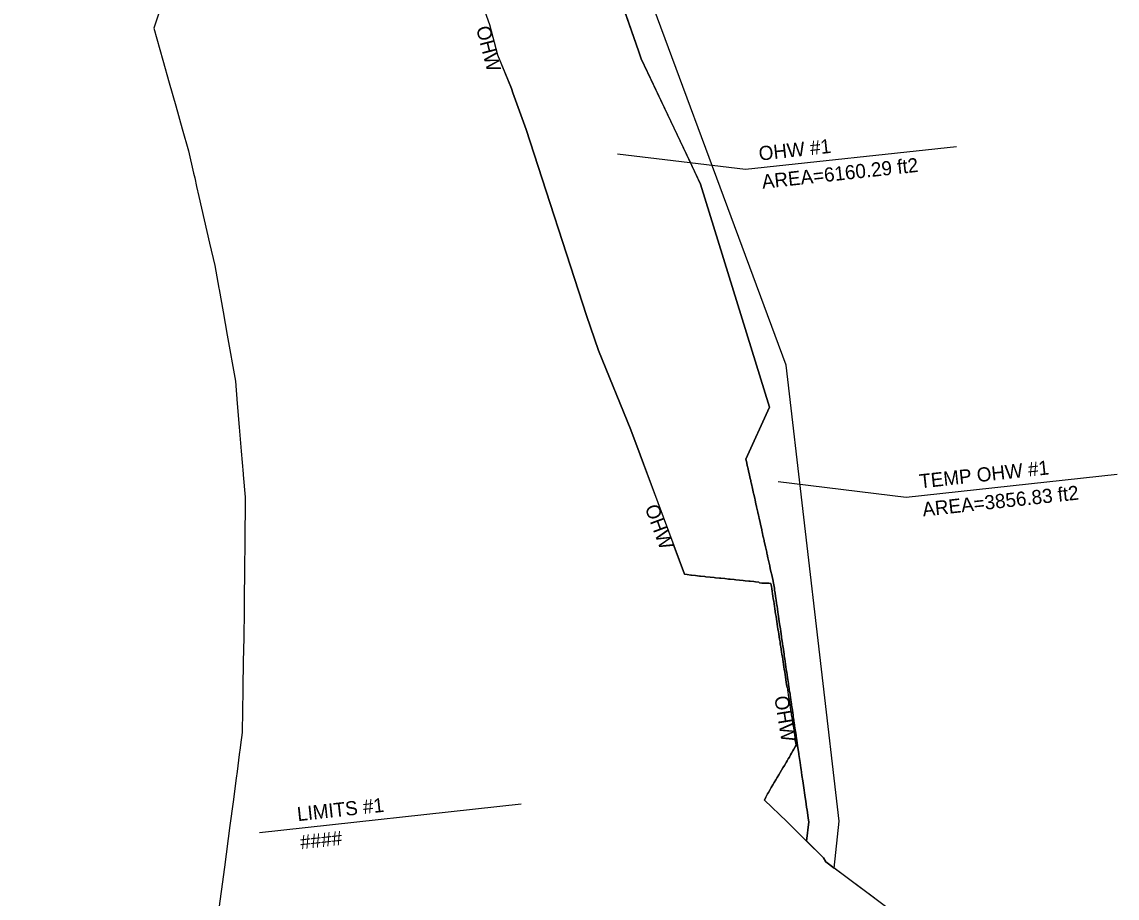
# Model space of a CAD drawing. Extents: x 1509537 to 1510685, y 401169 to 402194.
# Drawn here: x 1509714.7 to 1509931.6, y 401562.2 to 401735.7 of the extents above; entities that cross this region are included whole.
import ezdxf

# ---------------------------------------------------------------- set-up
doc = ezdxf.new("R2010")
doc.units = 0
for name, color, linetype in [('LAWE', 7, 'Continuous'), ('LAWE_P', 7, 'Continuous'), ('LAWE_P_T', 7, 'Continuous'), ('Level 6', 7, 'Continuous'), ('Level 9', 7, 'Continuous')]:
    doc.layers.add(name, color=color, linetype=linetype)

msp = doc.modelspace()

# ---------------------------------------------------------------- linework, layer by layer
at = {"layer": 'LAWE'}
for points in [[(1509840.19, 401641.87), (1509837.17, 401650.02), (1509835.36, 401654.93), (1509828.91, 401670.68), (1509826.52, 401677.61), (1509814.57, 401714.41), (1509811.96, 401721.64), (1509811.67, 401722.52), (1509809.89, 401726.86)], [(1509866.28, 401603.91), (1509866.27, 401603.95), (1509866.18, 401604.52), (1509866.12, 401604.95), (1509866.02, 401605.52), (1509865.96, 401605.95), (1509865.87, 401606.53), (1509865.8, 401606.95), (1509865.71, 401607.53), (1509865.65, 401607.95), (1509865.56, 401608.53), (1509865.49, 401608.95), (1509865.4, 401609.53), (1509865.34, 401609.95), (1509865.24, 401610.53), (1509865.18, 401610.95), (1509865.09, 401611.53), (1509865.03, 401611.95), (1509864.93, 401612.53), (1509864.87, 401612.95), (1509864.78, 401613.53), (1509864.71, 401613.96), (1509864.62, 401614.53), (1509864.56, 401614.96), (1509864.46, 401615.53), (1509864.4, 401615.96), (1509864.31, 401616.53), (1509864.25, 401616.96), (1509864.15, 401617.54), (1509864.09, 401617.96), (1509864, 401618.54), (1509863.94, 401618.96), (1509863.84, 401619.54), (1509863.78, 401619.96), (1509863.69, 401620.54), (1509863.62, 401620.96), (1509863.53, 401621.54), (1509863.47, 401621.96), (1509863.37, 401622.54), (1509863.31, 401622.96), (1509863.22, 401623.54), (1509863.16, 401623.96), (1509863.06, 401624.54), (1509862.66, 401624.58), (1509862.15, 401624.56), (1509861.73, 401624.6), (1509861.24, 401624.58), (1509860.8, 401624.62), (1509860.7, 401624.78), (1509860, 401624.86), (1509859.7, 401624.89), (1509858.98, 401624.96), (1509858.7, 401625), (1509857.97, 401625.07), (1509857.6, 401625.11), (1509856.87, 401625.18), (1509856.13, 401625.26), (1509855.78, 401625.3), (1509855.03, 401625.37), (1509854.7, 401625.41), (1509853.95, 401625.48), (1509853.17, 401625.56), (1509852.88, 401625.6), (1509852.09, 401625.67), (1509851.81, 401625.7), (1509851.03, 401625.78), (1509850.21, 401625.86), (1509849.97, 401625.89), (1509849.15, 401625.97), (1509848.93, 401626), (1509848.11, 401626.08), (1509847.37, 401626.17), (1509847.24, 401626.19), (1509846.49, 401626.29), (1509845.93, 401626.36), (1509843.7, 401632.37)], [(1509888.15, 401558.82), (1509873.96, 401569.39), (1509873.47, 401570.24), (1509866.19, 401577.38), (1509861.77, 401581.65), (1509862.07, 401582.21), (1509862.42, 401582.85), (1509862.6, 401583.15), (1509862.92, 401583.73), (1509863.15, 401584.11), (1509863.47, 401584.68), (1509863.72, 401585.12), (1509864.04, 401585.65), (1509864.3, 401586.1), (1509864.62, 401586.63), (1509864.88, 401587.07), (1509865.17, 401587.55), (1509865.45, 401588.01), (1509865.73, 401588.46), (1509866.01, 401588.93), (1509866.07, 401589.06), (1509866.27, 401589.39), (1509866.51, 401589.84), (1509866.72, 401590.17), (1509866.96, 401590.62), (1509867.16, 401590.95), (1509867.4, 401591.4), (1509867.6, 401591.73), (1509867.85, 401592.18), (1509868.05, 401592.51), (1509867.98, 401592.94), (1509867.89, 401593.51), (1509867.83, 401593.91)]]:
    msp.add_lwpolyline(points, dxfattribs=at)
at = {"layer": 'LAWE_P'}
for p, q in [((1509836.93, 401729.78), (1509831.74, 401744.61)), ((1509836.94, 401729.77), (1509836.93, 401729.78)), ((1509837.39, 401728.38), (1509836.94, 401729.77)), ((1509847.13, 401707.85), (1509837.39, 401728.38)), ((1509858.28, 401648.4), (1509858.13, 401649.11)), ((1509858.48, 401647.51), (1509858.46, 401647.63)), ((1509858.71, 401646.49), (1509858.48, 401647.51)), ((1509858.76, 401646.27), (1509858.71, 401646.49)), ((1509859.1, 401644.73), (1509859.06, 401644.94)), ((1509859.16, 401644.48), (1509859.1, 401644.73)), ((1509859.35, 401643.63), (1509859.29, 401643.9)), ((1509860.11, 401640.21), (1509859.92, 401641.09)), ((1509860.19, 401639.86), (1509860.11, 401640.21)), ((1509860.58, 401638.14), (1509860.49, 401638.53)), ((1509861.25, 401635.12), (1509860.99, 401636.27)), ((1509861.26, 401635.07), (1509861.25, 401635.12)), ((1509861.34, 401634.7), (1509861.26, 401635.07)), ((1509861.39, 401634.51), (1509861.34, 401634.7)), ((1509861.71, 401633.06), (1509861.59, 401633.58)), ((1509861.75, 401632.86), (1509861.71, 401633.06)), ((1509862.24, 401630.71), (1509862, 401631.76)), ((1509862.24, 401630.68), (1509862.24, 401630.71)), ((1509862.29, 401630.48), (1509862.24, 401630.68)), ((1509862.55, 401629.31), (1509862.48, 401629.61)), ((1509863.15, 401626.6), (1509862.95, 401627.52)), ((1509863.18, 401626.49), (1509863.15, 401626.6)), ((1509863.45, 401625.28), (1509863.18, 401626.49)), ((1509863.6, 401624.58), (1509863.45, 401625.28)), ((1509863.7, 401623.94), (1509863.6, 401624.58)), ((1509863.75, 401623.58), (1509863.7, 401623.94)), ((1509863.81, 401623.17), (1509863.75, 401623.58)), ((1509864.09, 401621.27), (1509864.05, 401621.57)), ((1509864.2, 401620.56), (1509864.09, 401621.27)), ((1509864.28, 401619.98), (1509864.2, 401620.56)), ((1509864.34, 401619.56), (1509864.28, 401619.98)), ((1509864.47, 401618.7), (1509864.34, 401619.56)), ((1509864.49, 401618.56), (1509864.47, 401618.7)), ((1509864.79, 401616.55), (1509864.66, 401617.44)), ((1509865.02, 401614.99), (1509864.94, 401615.54)), ((1509865.08, 401614.54), (1509865.02, 401614.99)), ((1509865.09, 401614.51), (1509865.08, 401614.54)), ((1509865.16, 401614.05), (1509865.09, 401614.51)), ((1509865.19, 401613.79), (1509865.16, 401614.05)), ((1509865.38, 401612.53), (1509865.37, 401612.61)), ((1509865.68, 401610.52), (1509865.54, 401611.44)), ((1509865.71, 401610.29), (1509865.68, 401610.52)), ((1509865.97, 401608.51), (1509865.88, 401609.15)), ((1509866.37, 401605.82), (1509866.27, 401606.5)), ((1509866.71, 401603.49), (1509866.69, 401603.65)), ((1509866.85, 401602.58), (1509866.71, 401603.49)), ((1509867.13, 401600.67), (1509867.01, 401601.48)), ((1509867.31, 401599.41), (1509867.31, 401599.47)), ((1509867.62, 401597.34), (1509867.6, 401597.46)), ((1509867.75, 401596.46), (1509867.62, 401597.34)), ((1509867.77, 401596.31), (1509867.75, 401596.46)), ((1509867.9, 401595.46), (1509867.77, 401596.31)), ((1509867.92, 401595.29), (1509867.9, 401595.46)), ((1509868.05, 401594.46), (1509867.92, 401595.29)), ((1509868.19, 401593.45), (1509868.07, 401594.27)), ((1509868.34, 401592.44), (1509868.19, 401593.45)), ((1509868.84, 401589.08), (1509868.61, 401590.64)), ((1509869.96, 401581.45), (1509869.86, 401582.13)), ((1509870.19, 401579.94), (1509870.14, 401580.26))]:
    msp.add_line(p, q, dxfattribs=at)
for points in [[(1509795.89, 401767.18), (1509807.37, 401735.22), (1509808.92, 401729.22), (1509811.67, 401722.52), (1509811.96, 401721.64), (1509814.57, 401714.41), (1509826.52, 401677.61), (1509828.91, 401670.68), (1509835.36, 401654.93), (1509837.17, 401650.02), (1509840.68, 401640.55), (1509845.93, 401626.36), (1509846.49, 401626.29), (1509847.24, 401626.19), (1509847.37, 401626.17), (1509848.11, 401626.08), (1509848.93, 401626), (1509849.15, 401625.97), (1509849.97, 401625.89), (1509850.21, 401625.86), (1509851.03, 401625.78), (1509851.81, 401625.7), (1509852.09, 401625.67), (1509852.88, 401625.6), (1509853.17, 401625.56), (1509853.95, 401625.48), (1509854.7, 401625.41), (1509855.03, 401625.37), (1509855.78, 401625.3), (1509856.13, 401625.26), (1509856.87, 401625.18), (1509857.6, 401625.11), (1509857.97, 401625.07), (1509858.7, 401625), (1509858.98, 401624.96), (1509859.7, 401624.89), (1509860, 401624.86), (1509860.7, 401624.78), (1509860.8, 401624.62), (1509861.24, 401624.58), (1509861.73, 401624.6), (1509862.15, 401624.56), (1509862.66, 401624.58), (1509863.06, 401624.54), (1509863.16, 401623.96), (1509863.22, 401623.54), (1509863.31, 401622.96), (1509863.37, 401622.54), (1509863.47, 401621.96), (1509863.53, 401621.54), (1509863.62, 401620.96), (1509863.69, 401620.54), (1509863.78, 401619.96), (1509863.84, 401619.54), (1509863.94, 401618.96), (1509864, 401618.54), (1509864.09, 401617.96), (1509864.15, 401617.54), (1509864.25, 401616.96), (1509864.31, 401616.53), (1509864.4, 401615.96), (1509864.46, 401615.53), (1509864.56, 401614.96), (1509864.62, 401614.53), (1509864.71, 401613.96), (1509864.78, 401613.53), (1509864.87, 401612.95), (1509864.93, 401612.53), (1509865.03, 401611.95), (1509865.09, 401611.53), (1509865.18, 401610.95), (1509865.24, 401610.53), (1509865.34, 401609.95), (1509865.4, 401609.53), (1509865.49, 401608.95), (1509865.56, 401608.53), (1509865.65, 401607.95), (1509865.71, 401607.53), (1509865.8, 401606.95), (1509865.87, 401606.53), (1509865.96, 401605.95), (1509866.02, 401605.52), (1509866.12, 401604.95), (1509866.18, 401604.52), (1509866.27, 401603.95), (1509866.33, 401603.52), (1509866.43, 401602.95), (1509866.49, 401602.52), (1509866.58, 401601.95), (1509866.65, 401601.52), (1509866.74, 401600.95), (1509866.8, 401600.52), (1509866.89, 401599.95), (1509866.96, 401599.52), (1509867.05, 401598.94), (1509867.11, 401598.52), (1509867.21, 401597.94), (1509867.27, 401597.52), (1509867.36, 401596.94), (1509867.42, 401596.52), (1509867.52, 401595.94), (1509867.58, 401595.51), (1509867.67, 401594.94), (1509867.74, 401594.51), (1509867.83, 401593.94), (1509867.89, 401593.51), (1509867.98, 401592.94), (1509868.05, 401592.51), (1509867.85, 401592.18), (1509867.6, 401591.73), (1509867.4, 401591.4), (1509867.16, 401590.95), (1509866.96, 401590.62), (1509866.72, 401590.17), (1509866.51, 401589.84), (1509866.27, 401589.39), (1509866.07, 401589.06), (1509866.01, 401588.93), (1509865.73, 401588.46), (1509865.45, 401588.01), (1509865.17, 401587.55), (1509864.88, 401587.07), (1509864.62, 401586.63), (1509864.3, 401586.1), (1509864.04, 401585.65), (1509863.72, 401585.12), (1509863.47, 401584.68), (1509863.15, 401584.11), (1509862.92, 401583.73), (1509862.6, 401583.15), (1509862.42, 401582.85), (1509862.07, 401582.21), (1509861.77, 401581.65), (1509866.19, 401577.38), (1509870.13, 401573.51)], [(1509858.13, 401649.11), (1509862.77, 401659.41), (1509849.15, 401703.58), (1509847.13, 401707.85)], [(1509858.46, 401647.63), (1509858.31, 401648.29), (1509858.28, 401648.4)], [(1509859.06, 401644.94), (1509858.98, 401645.3), (1509858.76, 401646.27)], [(1509859.29, 401643.9), (1509859.27, 401643.99), (1509859.16, 401644.48)], [(1509859.92, 401641.09), (1509859.86, 401641.35), (1509859.66, 401642.23), (1509859.64, 401642.35), (1509859.49, 401643.02), (1509859.35, 401643.63)], [(1509860.49, 401638.53), (1509860.46, 401638.64), (1509860.34, 401639.19), (1509860.22, 401639.72), (1509860.19, 401639.86)], [(1509860.73, 401637.45), (1509860.67, 401637.7), (1509860.58, 401638.14)], [(1509860.99, 401636.27), (1509860.92, 401636.58), (1509860.73, 401637.45)], [(1509861.59, 401633.58), (1509861.5, 401633.98), (1509861.39, 401634.51)], [(1509862, 401631.76), (1509861.92, 401632.13), (1509861.75, 401632.86)], [(1509862.48, 401629.61), (1509862.32, 401630.33), (1509862.29, 401630.48)], [(1509862.95, 401627.52), (1509862.85, 401627.94), (1509862.84, 401627.99), (1509862.72, 401628.56), (1509862.55, 401629.31)], [(1509864.05, 401621.57), (1509863.9, 401622.57), (1509863.9, 401622.6), (1509863.81, 401623.17)], [(1509864.66, 401617.44), (1509864.64, 401617.55), (1509864.5, 401618.47), (1509864.49, 401618.56)], [(1509864.94, 401615.54), (1509864.84, 401616.21), (1509864.79, 401616.55)], [(1509865.37, 401612.61), (1509865.23, 401613.53), (1509865.19, 401613.79)], [(1509865.54, 401611.44), (1509865.53, 401611.53), (1509865.38, 401612.53)], [(1509865.88, 401609.15), (1509865.82, 401609.52), (1509865.78, 401609.84), (1509865.71, 401610.29)], [(1509866.27, 401606.5), (1509866.21, 401606.92), (1509866.12, 401607.51), (1509866.04, 401608.03), (1509865.97, 401608.51)], [(1509866.53, 401604.73), (1509866.42, 401605.5), (1509866.37, 401605.82)], [(1509866.69, 401603.65), (1509866.57, 401604.5), (1509866.53, 401604.73)], [(1509867.01, 401601.48), (1509867, 401601.51), (1509866.94, 401601.93), (1509866.86, 401602.49), (1509866.85, 401602.58)], [(1509867.31, 401599.47), (1509867.16, 401600.46), (1509867.16, 401600.48), (1509867.13, 401600.67)], [(1509867.6, 401597.46), (1509867.5, 401598.15), (1509867.47, 401598.38), (1509867.45, 401598.47), (1509867.31, 401599.41)], [(1509868.07, 401594.27), (1509868.05, 401594.45), (1509868.05, 401594.46)], [(1509868.61, 401590.64), (1509868.58, 401590.81), (1509868.34, 401592.44)], [(1509869.65, 401583.58), (1509869.51, 401584.51), (1509869.37, 401585.46), (1509869.21, 401586.52), (1509869.12, 401587.19), (1509869.04, 401587.72), (1509868.99, 401588.03), (1509868.84, 401589.08)], [(1509869.86, 401582.13), (1509869.72, 401583.08), (1509869.65, 401583.58)], [(1509870.14, 401580.26), (1509870.05, 401580.83), (1509869.96, 401581.45)], [(1509870.13, 401573.51), (1509870.56, 401577.36), (1509870.47, 401578.03), (1509870.22, 401579.72), (1509870.19, 401579.94)]]:
    msp.add_lwpolyline(points, dxfattribs=at)
at = {"layer": 'LAWE_P_T'}
msp.add_line((1509761.82, 401575.22), (1509813.64, 401580.87), dxfattribs=at)
for points in [[(1509832.69, 401709.61), (1509858.05, 401706.52), (1509899.82, 401711.07)], [(1509864.49, 401644.73), (1509889.85, 401641.63), (1509931.62, 401646.19)]]:
    msp.add_lwpolyline(points, dxfattribs=at)
at = {"layer": 'Level 6'}
for p, q in [((1509836.94, 401729.77), (1509837.39, 401728.38)), ((1509858.13, 401649.11), (1509858.28, 401648.4)), ((1509858.28, 401648.4), (1509858.31, 401648.29)), ((1509859.06, 401644.94), (1509859.1, 401644.73)), ((1509859.1, 401644.73), (1509859.16, 401644.48)), ((1509859.49, 401643.02), (1509859.64, 401642.35)), ((1509859.64, 401642.35), (1509859.66, 401642.23)), ((1509859.66, 401642.23), (1509859.86, 401641.35)), ((1509859.86, 401641.35), (1509859.92, 401641.09)), ((1509859.92, 401641.09), (1509860.11, 401640.21)), ((1509860.11, 401640.21), (1509860.19, 401639.86)), ((1509860.19, 401639.86), (1509860.22, 401639.72)), ((1509860.22, 401639.72), (1509860.34, 401639.19)), ((1509860.49, 401638.53), (1509860.58, 401638.14)), ((1509860.92, 401636.58), (1509860.99, 401636.27)), ((1509861.34, 401634.7), (1509861.39, 401634.51)), ((1509861.71, 401633.06), (1509861.75, 401632.86)), ((1509861.75, 401632.86), (1509861.92, 401632.13)), ((1509862.24, 401630.68), (1509862.29, 401630.48)), ((1509862.29, 401630.48), (1509862.32, 401630.33)), ((1509862.32, 401630.33), (1509862.48, 401629.61)), ((1509862.48, 401629.61), (1509862.55, 401629.31)), ((1509862.55, 401629.31), (1509862.72, 401628.56)), ((1509863.15, 401626.6), (1509863.18, 401626.49)), ((1509863.18, 401626.49), (1509863.45, 401625.28)), ((1509863.7, 401623.94), (1509863.75, 401623.58)), ((1509863.9, 401622.6), (1509863.9, 401622.57)), ((1509863.9, 401622.57), (1509864.05, 401621.57)), ((1509864.05, 401621.57), (1509864.09, 401621.27)), ((1509864.09, 401621.27), (1509864.2, 401620.56)), ((1509864.2, 401620.56), (1509864.28, 401619.98)), ((1509864.28, 401619.98), (1509864.34, 401619.56)), ((1509864.34, 401619.56), (1509864.47, 401618.7)), ((1509864.47, 401618.7), (1509864.49, 401618.56)), ((1509864.49, 401618.56), (1509864.5, 401618.47)), ((1509864.66, 401617.44), (1509864.79, 401616.55)), ((1509864.79, 401616.55), (1509864.84, 401616.21)), ((1509864.84, 401616.21), (1509864.94, 401615.54)), ((1509865.08, 401614.54), (1509865.09, 401614.51)), ((1509865.09, 401614.51), (1509865.16, 401614.05)), ((1509865.37, 401612.61), (1509865.38, 401612.53)), ((1509865.38, 401612.53), (1509865.53, 401611.53)), ((1509865.53, 401611.53), (1509865.54, 401611.44)), ((1509865.54, 401611.44), (1509865.68, 401610.52)), ((1509865.68, 401610.52), (1509865.71, 401610.29)), ((1509865.71, 401610.29), (1509865.78, 401609.84)), ((1509865.78, 401609.84), (1509865.82, 401609.52)), ((1509865.82, 401609.52), (1509865.88, 401609.15)), ((1509866.21, 401606.92), (1509866.27, 401606.5)), ((1509866.42, 401605.5), (1509866.53, 401604.73)), ((1509866.85, 401602.58), (1509866.86, 401602.49)), ((1509866.86, 401602.49), (1509866.94, 401601.93)), ((1509866.94, 401601.93), (1509867, 401601.51)), ((1509867, 401601.51), (1509867.01, 401601.48)), ((1509867.01, 401601.48), (1509867.13, 401600.67)), ((1509867.16, 401600.46), (1509867.31, 401599.47)), ((1509867.31, 401599.47), (1509867.31, 401599.41)), ((1509867.31, 401599.41), (1509867.45, 401598.47)), ((1509867.45, 401598.47), (1509867.47, 401598.38)), ((1509867.62, 401597.34), (1509867.75, 401596.46)), ((1509867.75, 401596.46), (1509867.77, 401596.31)), ((1509867.77, 401596.31), (1509867.9, 401595.46)), ((1509867.9, 401595.46), (1509867.92, 401595.29)), ((1509867.92, 401595.29), (1509868.05, 401594.46)), ((1509868.05, 401594.46), (1509868.05, 401594.45)), ((1509868.05, 401594.45), (1509868.07, 401594.27)), ((1509868.07, 401594.27), (1509868.19, 401593.45)), ((1509868.19, 401593.45), (1509868.34, 401592.44)), ((1509868.61, 401590.64), (1509868.84, 401589.08)), ((1509868.84, 401589.08), (1509868.99, 401588.03)), ((1509868.99, 401588.03), (1509869.04, 401587.72)), ((1509869.37, 401585.46), (1509869.51, 401584.51)), ((1509869.51, 401584.51), (1509869.65, 401583.58)), ((1509869.86, 401582.13), (1509869.96, 401581.45)), ((1509869.96, 401581.45), (1509870.05, 401580.83)), ((1509870.19, 401579.94), (1509870.22, 401579.72)), ((1509870.22, 401579.72), (1509870.47, 401578.03)), ((1509870.56, 401577.36), (1509870.13, 401573.51)), ((1509870.47, 401578.03), (1509870.56, 401577.36))]:
    msp.add_line(p, q, dxfattribs=at)
for points in [[(1509875.57, 401568.19), (1509876.61, 401577.47), (1509866.1, 401667.73), (1509829.75, 401765.91), (1509741.2, 401959.3), (1509714.74, 401967.81)], [(1509831.74, 401744.61), (1509836.93, 401729.78), (1509836.94, 401729.77)], [(1509837.39, 401728.38), (1509849.15, 401703.58), (1509862.77, 401659.41), (1509858.13, 401649.11)], [(1509858.31, 401648.29), (1509858.46, 401647.63), (1509858.48, 401647.51)], [(1509858.48, 401647.51), (1509858.71, 401646.49), (1509858.76, 401646.27), (1509858.98, 401645.3), (1509859.06, 401644.94)], [(1509859.16, 401644.48), (1509859.27, 401643.99), (1509859.29, 401643.9)], [(1509859.29, 401643.9), (1509859.35, 401643.63), (1509859.49, 401643.02)], [(1509860.34, 401639.19), (1509860.46, 401638.64), (1509860.49, 401638.53)], [(1509860.58, 401638.14), (1509860.67, 401637.7), (1509860.73, 401637.45), (1509860.92, 401636.58)], [(1509860.99, 401636.27), (1509861.25, 401635.12), (1509861.26, 401635.07), (1509861.34, 401634.7)], [(1509861.39, 401634.51), (1509861.5, 401633.98), (1509861.59, 401633.58), (1509861.71, 401633.06)], [(1509861.92, 401632.13), (1509862, 401631.76), (1509862.24, 401630.71), (1509862.24, 401630.68)], [(1509862.72, 401628.56), (1509862.84, 401627.99), (1509862.85, 401627.94)], [(1509862.85, 401627.94), (1509862.95, 401627.52), (1509863.15, 401626.6)], [(1509863.45, 401625.28), (1509863.6, 401624.58), (1509863.7, 401623.94)], [(1509863.75, 401623.58), (1509863.81, 401623.17), (1509863.9, 401622.6)], [(1509864.5, 401618.47), (1509864.64, 401617.55), (1509864.66, 401617.44)], [(1509864.94, 401615.54), (1509865.02, 401614.99), (1509865.08, 401614.54)], [(1509865.16, 401614.05), (1509865.19, 401613.79), (1509865.23, 401613.53), (1509865.37, 401612.61)], [(1509865.88, 401609.15), (1509865.97, 401608.51), (1509866.04, 401608.03), (1509866.12, 401607.51), (1509866.21, 401606.92)], [(1509866.27, 401606.5), (1509866.37, 401605.82), (1509866.42, 401605.5)], [(1509866.53, 401604.73), (1509866.57, 401604.5), (1509866.69, 401603.65), (1509866.71, 401603.49), (1509866.85, 401602.58)], [(1509867.13, 401600.67), (1509867.16, 401600.48), (1509867.16, 401600.46)], [(1509867.47, 401598.38), (1509867.5, 401598.15), (1509867.6, 401597.46), (1509867.62, 401597.34)], [(1509868.34, 401592.44), (1509868.58, 401590.81), (1509868.61, 401590.64)], [(1509869.04, 401587.72), (1509869.12, 401587.19), (1509869.21, 401586.52), (1509869.37, 401585.46)], [(1509869.65, 401583.58), (1509869.72, 401583.08), (1509869.86, 401582.13)], [(1509870.05, 401580.83), (1509870.14, 401580.26), (1509870.19, 401579.94)], [(1509870.13, 401573.51), (1509873.47, 401570.24), (1509873.96, 401569.39), (1509875.57, 401568.19)]]:
    msp.add_lwpolyline(points, dxfattribs=at)
at = {"layer": 'Level 9'}
msp.add_line((1509883.57, 401562.24), (1509875.57, 401568.19), dxfattribs=at)
for points in [[(1509875.57, 401568.19), (1509876.61, 401577.47), (1509866.1, 401667.73), (1509829.75, 401765.91), (1509741.2, 401959.3), (1509714.74, 401967.81)], [(1509744.47, 401745.41), (1509740.85, 401734.45), (1509742.63, 401728.16), (1509743.92, 401723.63), (1509745.2, 401719.1), (1509746.48, 401714.56), (1509747.73, 401710.17), (1509748.75, 401705.73), (1509748.96, 401704.81), (1509749.35, 401703.13), (1509749.81, 401701.13), (1509750.86, 401696.53), (1509751.92, 401691.93), (1509752.95, 401687.47), (1509753.75, 401682.97), (1509753.79, 401682.76), (1509754.57, 401678.32), (1509755.4, 401673.66), (1509757.01, 401664.61), (1509757.38, 401660.18), (1509757.78, 401655.46), (1509758.17, 401650.75), (1509758.55, 401646.24), (1509758.57, 401646.03), (1509758.94, 401641.6), (1509758.86, 401632.41), (1509758.82, 401627.68), (1509758.8, 401625.63), (1509758.78, 401622.95), (1509758.74, 401618.26), (1509758.68, 401614.66), (1509758.66, 401613.56), (1509758.63, 401611.67), (1509758.58, 401608.84), (1509758.5, 401604.12), (1509758.49, 401603.34), (1509758.43, 401599.41), (1509758.36, 401595.03), (1509758.03, 401592.55), (1509757.96, 401591.99), (1509757.78, 401590.67), (1509757.35, 401587.32), (1509757.17, 401585.98), (1509756.56, 401581.3), (1509755.95, 401576.63), (1509754.87, 401568.33), (1509750.72, 401537.98)]]:
    msp.add_lwpolyline(points, dxfattribs=at)

# ---------------------------------------------------------------- texts
at = {"layer": 'LAWE'}
for rotation, p in [(284.4855, (1509804.66, 401734.52)), (290.2998, (1509838.05, 401639.58)), (279.1768, (1509863.73, 401602.07))]:
    msp.add_text('OHW', height=2.8, rotation=rotation, dxfattribs=at).set_placement(p)
at = {"layer": 'LAWE_P_T'}
for s, p in [('OHW #1', (1509860.81, 401708.23)), ('AREA=6160.29 ft2', (1509861.42, 401702.66)), ('TEMP OHW #1', (1509892.61, 401643.34)), ('AREA=3856.83 ft2', (1509893.21, 401637.78)), ('LIMITS #1', (1509769.39, 401577.46)), ('####', (1509770, 401571.89))]:
    msp.add_text(s, height=2.8, rotation=6.2219, dxfattribs=at).set_placement(p)

doc.saveas('drawing.dxf')
